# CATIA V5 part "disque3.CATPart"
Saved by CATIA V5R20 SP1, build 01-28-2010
Part number: disque1
Bounding box of the stored display mesh (mm): x 56 to 104, y 0 to 15, z 76.175 to 123.825
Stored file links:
  E:\EDELI\gcausse\Edeli_2012_233_gcausse\disque3.CATPart
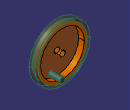
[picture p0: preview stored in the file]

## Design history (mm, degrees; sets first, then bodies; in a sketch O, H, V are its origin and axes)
Body1 (main body)
  DatumSurface1
  Sketch1 on face of DatumSurface1, origin (0, 5, 0), H (1, 0, 0), V (0, 0, 1)
    circle A1 centre (80, 100) radius 19
    circle A2 centre (80, 100) radius 2.5
    radius A1 = 19
    radius A2 = 2.5
  Pad1: profile Sketch1, direction (0, -1, 0), length 5
Body2
  Sketch2 on start face of Pad1, origin (0, 5, 0), H (-1, 0, 0), V (0, 0, 1)
    circle A1 centre (-80, 100) radius 21.5
    circle A2 centre (-80, 100) radius 19
    radius A2 = 19
    radius A1 = 21.5
  Pad2: profile Sketch2, direction (0, -1, 0), length 5
  Sketch3 on start face of Pad1, origin (0, 5, 0), H (-1, 0, 0), V (0, 0, 1)
Body3
  Sketch4 on start face of Pad1, origin (0, 5, 0), H (-1, 0, 0), V (0, 0, 1)
    circle A1 centre (-80, 100) radius 24
    circle A2 centre (-80, 100) radius 21.5
    radius A2 = 21.5
    radius A1 = 24
  Pad3: profile Sketch4, direction (0, -1, 0), length 5
  Sketch5 on start face of Pad1, origin (0, 5, 0), H (-1, 0, 0), V (0, 0, 1)
    circle A1 centre (-90, 90) radius 2.5
    radius A1 = 2.5
  Pad4: profile Sketch5, direction (0, 1, 0), length 10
